(* Logix 5000 project; controller AMCI_3204_AOP_AOI_sample_RSLogix_V28 vendor 1 type 14 code 92 rev 28.11; software revision 28.00; part 3 of 3 *)

VAR_GLOBAL   (* controller tags *)
   blend_data_3204_ch1 : DINT[52];
        [11]   // Segment 3 speed
        [13]   // Segment 4 length
        [15]   // Segment 4 Acceleration or Deceleration
        [17]   // Segment 5 speed
        [1]   // Number of Segments
        [3]   // Final Segment's Deceleration Value and Type
        [5]   // Segment 1 speed
        [7]   // Segment 2 length
        [9]   // Segment 2 Acceleration or Deceleration
        [10]   // Segment 3 length
        [12]   // Segment 3 Acceleration or Deceleration
        [14]   // Segment 4 speed
        [16]   // Segment 5 length
        [18]   // Segment 5 Acceleraiton or Deceleration
        [0]   // channel number (1 or 2)
        [2]   // Acceleration Type
        [4]   // Segment 1 length
        [6]   // Segment 1 Acceleration or Deceleration
        [8]   // Segment 2 speed
   blend_message_3204_ch1 : MESSAGE;
        .DN   // set when blend data has been programmed
        MessageParameters(ServiceCode := 16#004c, LocalElement := blend_data_3204_ch1[0], ...)
   buffered_3204_data : DINT[20];
        [10].31   // AMCI 3204 ch 3 mode bit 1=config mode 0=command mode
        [0].1   // set when CCW motion is occurring on ch 1 of the AMCI 3204 module
        [10].13   // set when AMCI 3204 ch 3 has a configuration error
        [15].13   // set when AMCI 3204 ch 4 has a configuration error
        [15].31   // AMCI 3204 ch 4 mode bit 1=config mode 0=command mode
        [0].0   // set when CW motion is occurring on ch 1 of the AMCI 3204 module
        [0].7   // AMCI 3204 move complete bit
        [0].28   // set when AMCI 3204 ch 1 is disabled
        [5].28   // set when AMCI 3204 ch 2 is disabled
        [10].28   // Set when 3204 channel 3 is disabled
        [15].28   // Set when 3204 channel 4 is disabled
        [0].10   // AMCI 3204 ch 1 position invalid bit
        [0].13   // set when AMCI 3204 ch 1 has a configuration error
        [0].31   // AMCI 3204 ch 1 mode bit 1=config mode 0=command mode
        [5].13   // set when AMCI 3204 ch 2 has a configuration error
        [5].31   // AMCI 3204 ch 2 mode bit 1=config mode 0=command mode
   comment : INT;
   configure_3204_ch1 : DINT[5] := ([0] := -2146500561, [1] := 100);
        [1]   // starting speed
        [0]   // configuration word
   configure_3204_ch2 : DINT[5] := ([0] := -2146500561, [1] := 100);
        [1]   // starting speed
        [0]   // configuration word
   configure_3204_ch3 : DINT[5] := ([0] := -2146500561, [1] := 100);
        [0]   // configuration word
        [1]   // starting speed
   configure_3204_ch4 : DINT[5] := ([0] := -2146500561, [1] := 100);
        [0]   // configuration word
        [1]   // starting speed
   one_shot_1 : BOOL;
   one_shot_2 : BOOL;
   run_3204_ch1 : INT;   // 1=run relative move 2=CW Manual Move 3=CCW Manual Move 4=Reset Errors 5=Home CW 6=Preset 7=Program Blend 8=Run Blend CW
   run_3204_ch2 : INT;
   run_3204_ch3 : INT;
   run_3204_ch4 : INT;
END_VAR

PROGRAM MainProgram   (* main routine MainRoutine *)
VAR
   AMCI_3204_ch1_absolute_move_aoi : AMCI_3204_AOP_Absolute_Move;
   AMCI_3204_ch1_CCW_manual_move_AOI : AMCI_3204_AOP_Manual_Move_CCW;
   AMCI_3204_ch1_config_AOI : AMCI_3204_AOP_Configure;
   AMCI_3204_ch1_CW_manual_move_aoi : AMCI_3204_AOP_Manual_Move_CW;
   AMCI_3204_ch1_hold_AOI : AMCI_3204_AOP_Hold;
   AMCI_3204_ch1_Home_CCW_AOI : AMCI_3204_AOP_Home_CCW;
   AMCI_3204_ch1_Home_CW_AOI : AMCI_3204_AOP_Home_CW;
   AMCI_3204_ch1_immediate_stop_AOI : AMCI_3204_AOP_Immediate_Stop;
   AMCI_3204_ch1_preset_AOI : AMCI_3204_AOP_Preset;
   AMCI_3204_ch1_relative_move_AOI : AMCI_3204_AOP_Relative_Move;
   AMCI_3204_ch1_reset_errors_AOI : AMCI_3204_AOP_Reset_Errors;
   AMCI_3204_ch1_resume_AOI : AMCI_3204_AOP_Resume;
   AMCI_3204_ch1_run_blend : AMCI_3204_AOP_Run_Blend;
   AMCI_3204_ch2_config_AOI : AMCI_3204_AOP_Configure;
   AMCI_3204_ch2_CW_manual_move_aoi : AMCI_3204_AOP_Manual_Move_CW;
   AMCI_3204_ch2_relative_move_AOI : AMCI_3204_AOP_Relative_Move;
   AMCI_3204_ch3_config_AOI : AMCI_3204_AOP_Configure;
   AMCI_3204_ch3_CW_manual_move_aoi : AMCI_3204_AOP_Manual_Move_CW;
   AMCI_3204_ch3_relative_move_AOI : AMCI_3204_AOP_Relative_Move;
   AMCI_3204_ch4_config_AOI : AMCI_3204_AOP_Configure;
   AMCI_3204_ch4_CW_manual_move_aoi : AMCI_3204_AOP_Manual_Move_CW;
   AMCI_3204_ch4_relative_move_AOI : AMCI_3204_AOP_Relative_Move;
END_VAR

ROUTINE Channel_1_3204   (* ladder *)
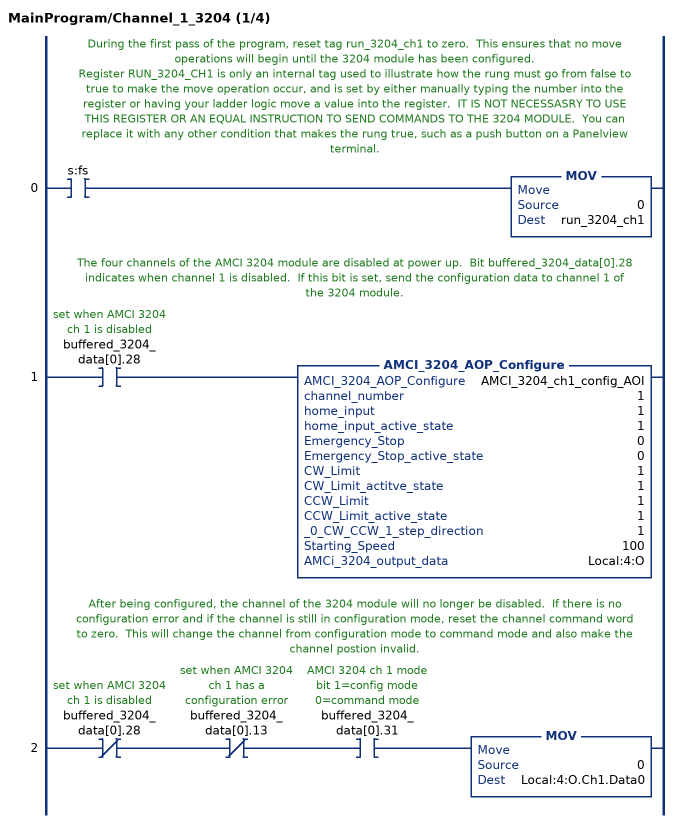
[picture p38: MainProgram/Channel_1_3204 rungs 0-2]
   // During the first pass of the program, reset tag run_3204_ch1 to zero.  This ensures that no move operations will begin until the 3204 module has been configured.
   // Register RUN_3204_CH1 is only an internal tag used to illustrate how the rung must go from false to true to make the move operation occur, and is set by either manually typing the number into the register or having your ladder logic move a value into the register.  IT IS NOT NECESSASRY TO USE THIS REGISTER OR AN EQUAL INSTRUCTION TO SEND COMMANDS TO THE 3204 MODULE.  You can replace it with any other condition that makes the rung true, such as a push button on a Panelview terminal.
   0: XIC(s:fs)MOV(0,run_3204_ch1);
   // The four channels of the AMCI 3204 module are disabled at power up.  Bit buffered_3204_data[0].28 indicates when channel 1 is disabled.  If this bit is set, send the configuration data to channel 1 of the 3204 module.
   1: XIC(buffered_3204_data[0].28)AMCI_3204_AOP_Configure(AMCI_3204_ch1_config_AOI,1,1,1,0,0,1,1,1,1,1,100,Local:4:O);
   // After being configured, the channel of the 3204 module will no longer be disabled.  If there is no configuration error and if the channel is still in configuration mode, reset the channel command word to zero.  This will change the channel from configuration mode to command mode and also make the channel postion invalid.
   2: XIO(buffered_3204_data[0].28)XIO(buffered_3204_data[0].13)XIC(buffered_3204_data[0].31)MOV(0,Local:4:O.Ch1.Data0);
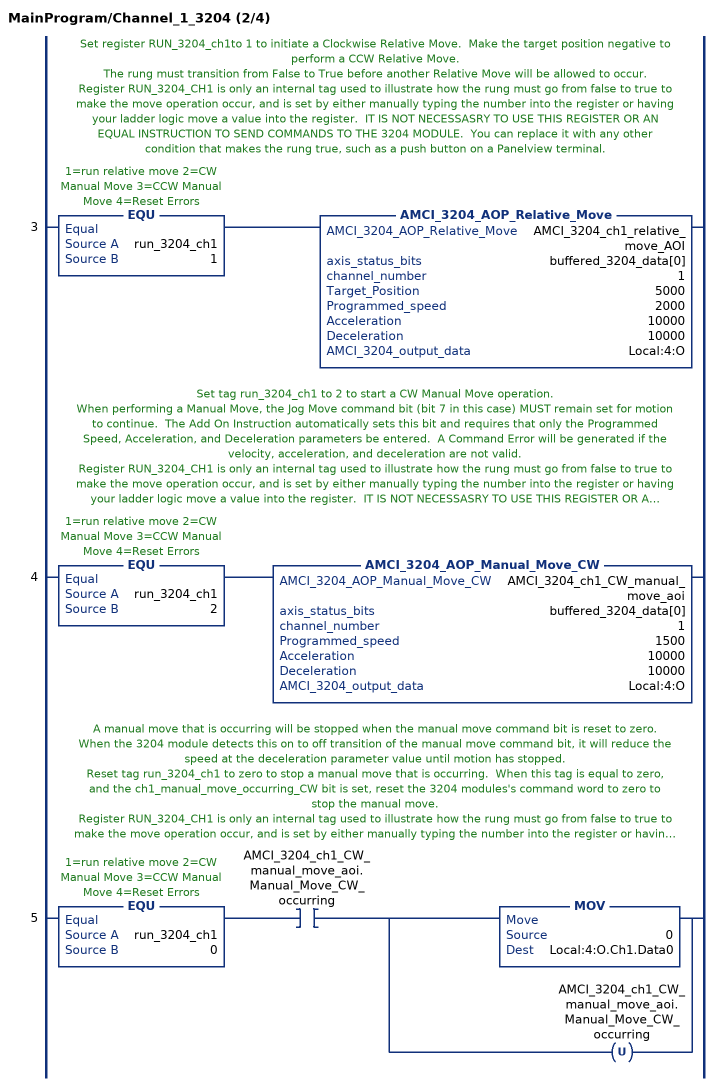
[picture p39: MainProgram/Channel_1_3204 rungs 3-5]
   // Set register RUN_3204_ch1to 1 to initiate a Clockwise Relative Move.  Make the target position negative to perform a CCW Relative Move.
   // The rung must transition from False to True before another Relative Move will be allowed to occur.
   // Register RUN_3204_CH1 is only an internal tag used to illustrate how the rung must go from false to true to make the move operation occur, and is set by either manually typing the number into the register or having your ladder logic move a value into the register.  IT IS NOT NECESSASRY TO USE THIS REGISTER OR AN EQUAL INSTRUCTION TO SEND COMMANDS TO THE 3204 MODULE.  You can replace it with any other condition that makes the rung true, such as a push button on a Panelview terminal.
   3: EQU(run_3204_ch1,1)AMCI_3204_AOP_Relative_Move(AMCI_3204_ch1_relative_move_AOI,buffered_3204_data[0],1,5000,2000,10000,10000,Local:4:O);
   // Set tag run_3204_ch1 to 2 to start a CW Manual Move operation.
   // When performing a Manual Move, the Jog Move command bit (bit 7 in this case) MUST remain set for motion to continue.  The Add On Instruction automatically sets this bit and requires that only the Programmed Speed, Acceleration, and Deceleration parameters be entered.  A Command Error will be generated if the velocity, acceleration, and deceleration are not valid.
   // Register RUN_3204_CH1 is only an internal tag used to illustrate how the rung must go from false to true to make the move operation occur, and is set by either manually typing the number into the register or having your ladder logic move a value into the register.  IT IS NOT NECESSASRY TO USE THIS REGISTER OR AN EQUAL INSTRUCTION TO SEND COMMANDS TO THE 3204 MODULE.  You can replace it with any other condition that makes the rung true, such as a push button on a Panelview terminal.
   4: EQU(run_3204_ch1,2)AMCI_3204_AOP_Manual_Move_CW(AMCI_3204_ch1_CW_manual_move_aoi,buffered_3204_data[0],1,1500,10000,10000,Local:4:O);
   // A manual move that is occurring will be stopped when the manual move command bit is reset to zero.  When the 3204 module detects this on to off transition of the manual move command bit, it will reduce the speed at the deceleration parameter value until motion has stopped.
   // Reset tag run_3204_ch1 to zero to stop a manual move that is occurring.  When this tag is equal to zero, and the ch1_manual_move_occurring_CW bit is set, reset the 3204 modules's command word to zero to stop the manual move.
   // Register RUN_3204_CH1 is only an internal tag used to illustrate how the rung must go from false to true to make the move operation occur, and is set by either manually typing the number into the register or having your ladder logic move a value into the register.  IT IS NOT NECESSASRY TO USE THIS REGISTER OR AN EQUAL INSTRUCTION TO SEND COMMANDS TO THE 3204 MODULE.  You can replace it with any other condition that makes the rung true, such as a push button on a Panelview terminal.
   5: EQU(run_3204_ch1,0)XIC(AMCI_3204_ch1_CW_manual_move_aoi.Manual_Move_CW_occurring)[MOV(0,Local:4:O.Ch1.Data0) ,OTU(AMCI_3204_ch1_CW_manual_move_aoi.Manual_Move_CW_occurring) ];
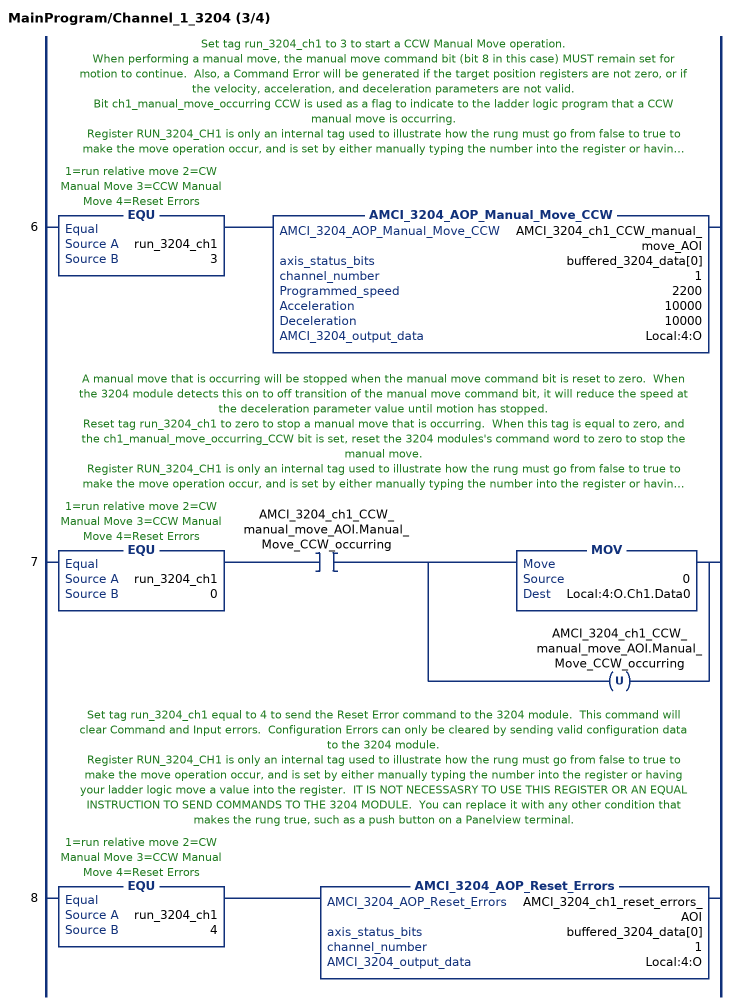
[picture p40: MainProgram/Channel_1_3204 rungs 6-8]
   // Set tag run_3204_ch1 to 3 to start a CCW Manual Move operation.
   // When performing a manual move, the manual move command bit (bit 8 in this case) MUST remain set for motion to continue.  Also, a Command Error will be generated if the target position registers are not zero, or if the velocity, acceleration, and deceleration parameters are not valid.
   // Bit ch1_manual_move_occurring CCW is used as a flag to indicate to the ladder logic program that a CCW manual move is occurring.
   // Register RUN_3204_CH1 is only an internal tag used to illustrate how the rung must go from false to true to make the move operation occur, and is set by either manually typing the number into the register or having your ladder logic move a value into the register.  IT IS NOT NECESSASRY TO USE THIS REGISTER OR AN EQUAL INSTRUCTION TO SEND COMMANDS TO THE 3204 MODULE.  You can replace it with any other condition that makes the rung true, such as a push button on a Panelview terminal.
   6: EQU(run_3204_ch1,3)AMCI_3204_AOP_Manual_Move_CCW(AMCI_3204_ch1_CCW_manual_move_AOI,buffered_3204_data[0],1,2200,10000,10000,Local:4:O);
   // A manual move that is occurring will be stopped when the manual move command bit is reset to zero.  When the 3204 module detects this on to off transition of the manual move command bit, it will reduce the speed at the deceleration parameter value until motion has stopped.
   // Reset tag run_3204_ch1 to zero to stop a manual move that is occurring.  When this tag is equal to zero, and the ch1_manual_move_occurring_CCW bit is set, reset the 3204 modules's command word to zero to stop the manual move.
   // Register RUN_3204_CH1 is only an internal tag used to illustrate how the rung must go from false to true to make the move operation occur, and is set by either manually typing the number into the register or having your ladder logic move a value into the register.  IT IS NOT NECESSASRY TO USE THIS REGISTER OR AN EQUAL INSTRUCTION TO SEND COMMANDS TO THE 3204 MODULE.  You can replace it with any other condition that makes the rung true, such as a push button on a Panelview terminal.
   7: EQU(run_3204_ch1,0)XIC(AMCI_3204_ch1_CCW_manual_move_AOI.Manual_Move_CCW_occurring)[MOV(0,Local:4:O.Ch1.Data0) ,OTU(AMCI_3204_ch1_CCW_manual_move_AOI.Manual_Move_CCW_occurring) ];
   // Set tag run_3204_ch1 equal to 4 to send the Reset Error command to the 3204 module.  This command will clear Command and Input errors.  Configuration Errors can only be cleared by sending valid configuration data to the 3204 module.
   // Register RUN_3204_CH1 is only an internal tag used to illustrate how the rung must go from false to true to make the move operation occur, and is set by either manually typing the number into the register or having your ladder logic move a value into the register.  IT IS NOT NECESSASRY TO USE THIS REGISTER OR AN EQUAL INSTRUCTION TO SEND COMMANDS TO THE 3204 MODULE.  You can replace it with any other condition that makes the rung true, such as a push button on a Panelview terminal.
   8: EQU(run_3204_ch1,4)AMCI_3204_AOP_Reset_Errors(AMCI_3204_ch1_reset_errors_AOI,buffered_3204_data[0],1,Local:4:O);
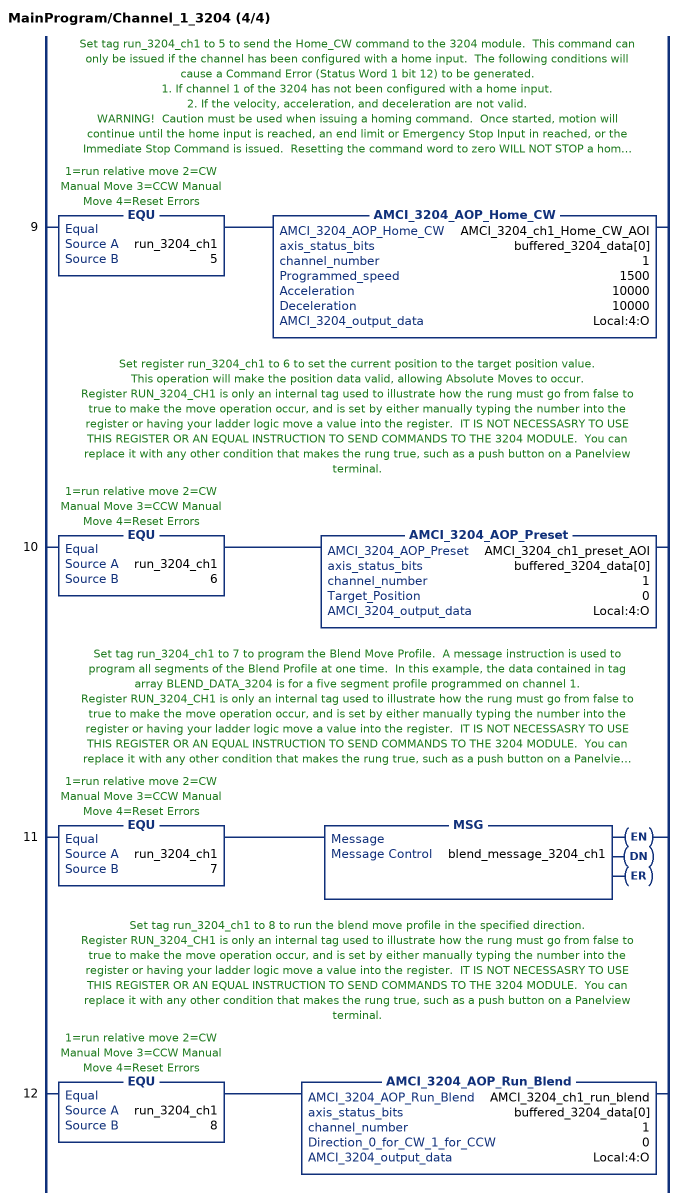
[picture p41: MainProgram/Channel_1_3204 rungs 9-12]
   // Set tag run_3204_ch1 to 5 to send the Home_CW command to the 3204 module.  This command can only be issued if the channel has been configured with a home input.  The following conditions will cause a Command Error (Status Word 1 bit 12) to be generated.
   // 1. If channel 1 of the 3204 has not been configured with a home input.
   // 2. If the velocity, acceleration, and deceleration are not valid.
   // WARNING!  Caution must be used when issuing a homing command.  Once started, motion will continue until the home input is reached, an end limit or Emergency Stop Input in reached, or the Immediate Stop Command is issued.  Resetting the command word to zero WILL NOT STOP a home operation.
   // Register RUN_3204_CH1 is only an internal tag used to illustrate how the rung must go from false to true to make the move operation occur, and is set by either manually typing the number into the register or having your ladder logic move a value into the register.  IT IS NOT NECESSASRY TO USE THIS REGISTER OR AN EQUAL INSTRUCTION TO SEND COMMANDS TO THE 3204 MODULE.  You can replace it with any other condition that makes the rung true, such as a push button on a Panelview terminal.
   9: EQU(run_3204_ch1,5)AMCI_3204_AOP_Home_CW(AMCI_3204_ch1_Home_CW_AOI,buffered_3204_data[0],1,1500,10000,10000,Local:4:O);
   // Set register run_3204_ch1 to 6 to set the current position to the target position value.
   // This operation will make the position data valid, allowing Absolute Moves to occur.
   // Register RUN_3204_CH1 is only an internal tag used to illustrate how the rung must go from false to true to make the move operation occur, and is set by either manually typing the number into the register or having your ladder logic move a value into the register.  IT IS NOT NECESSASRY TO USE THIS REGISTER OR AN EQUAL INSTRUCTION TO SEND COMMANDS TO THE 3204 MODULE.  You can replace it with any other condition that makes the rung true, such as a push button on a Panelview terminal.
   10: EQU(run_3204_ch1,6)AMCI_3204_AOP_Preset(AMCI_3204_ch1_preset_AOI,buffered_3204_data[0],1,0,Local:4:O);
   // Set tag run_3204_ch1 to 7 to program the Blend Move Profile.  A message instruction is used to program all segments of the Blend Profile at one time.  In this example, the data contained in tag array BLEND_DATA_3204 is for a five segment profile programmed on channel 1.
   // Register RUN_3204_CH1 is only an internal tag used to illustrate how the rung must go from false to true to make the move operation occur, and is set by either manually typing the number into the register or having your ladder logic move a value into the register.  IT IS NOT NECESSASRY TO USE THIS REGISTER OR AN EQUAL INSTRUCTION TO SEND COMMANDS TO THE 3204 MODULE.  You can replace it with any other condition that makes the rung true, such as a push button on a Panelview terminal.
   11: EQU(run_3204_ch1,7)MSG(blend_message_3204_ch1);
   // Set tag run_3204_ch1 to 8 to run the blend move profile in the specified direction.
   // Register RUN_3204_CH1 is only an internal tag used to illustrate how the rung must go from false to true to make the move operation occur, and is set by either manually typing the number into the register or having your ladder logic move a value into the register.  IT IS NOT NECESSASRY TO USE THIS REGISTER OR AN EQUAL INSTRUCTION TO SEND COMMANDS TO THE 3204 MODULE.  You can replace it with any other condition that makes the rung true, such as a push button on a Panelview terminal.
   12: EQU(run_3204_ch1,8)AMCI_3204_AOP_Run_Blend(AMCI_3204_ch1_run_blend,buffered_3204_data[0],1,0,Local:4:O);
END_ROUTINE

ROUTINE Channel_2_3204   (* ladder *)
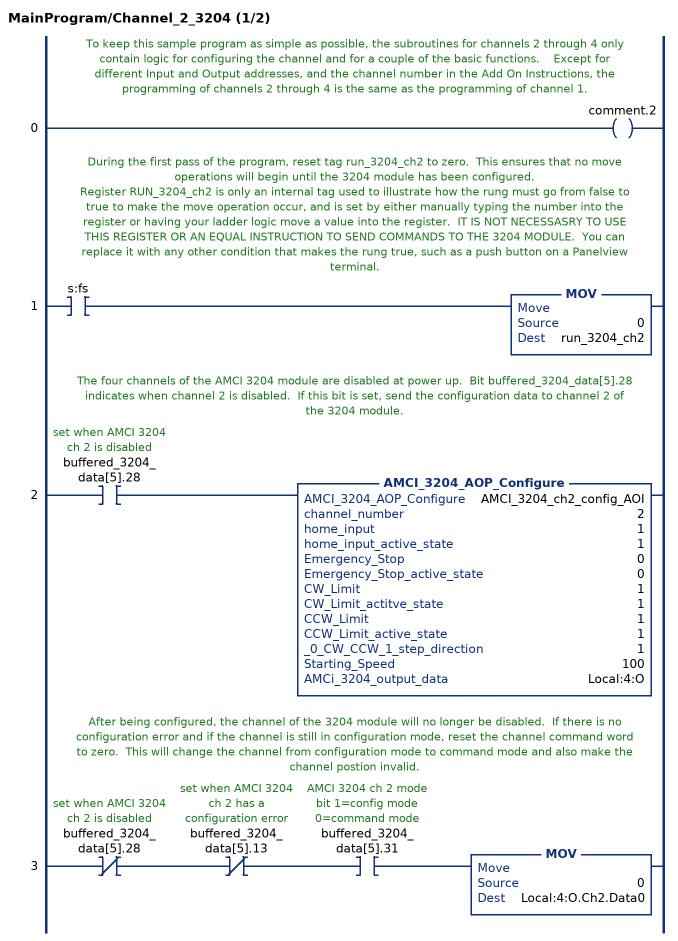
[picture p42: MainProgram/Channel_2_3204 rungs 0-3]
   // To keep this sample program as simple as possible, the subroutines for channels 2 through 4 only contain logic for configuring the channel and for a couple of the basic functions.    Except for different Input and Output addresses, and the channel number in the Add On Instructions, the programming of channels 2 through 4 is the same as the programming of channel 1.
   0: OTE(comment.2);
   // During the first pass of the program, reset tag run_3204_ch2 to zero.  This ensures that no move operations will begin until the 3204 module has been configured.
   // Register RUN_3204_ch2 is only an internal tag used to illustrate how the rung must go from false to true to make the move operation occur, and is set by either manually typing the number into the register or having your ladder logic move a value into the register.  IT IS NOT NECESSASRY TO USE THIS REGISTER OR AN EQUAL INSTRUCTION TO SEND COMMANDS TO THE 3204 MODULE.  You can replace it with any other condition that makes the rung true, such as a push button on a Panelview terminal.
   1: XIC(s:fs)MOV(0,run_3204_ch2);
   // The four channels of the AMCI 3204 module are disabled at power up.  Bit buffered_3204_data[5].28 indicates when channel 2 is disabled.  If this bit is set, send the configuration data to channel 2 of the 3204 module.
   2: XIC(buffered_3204_data[5].28)AMCI_3204_AOP_Configure(AMCI_3204_ch2_config_AOI,2,1,1,0,0,1,1,1,1,1,100,Local:4:O);
   // After being configured, the channel of the 3204 module will no longer be disabled.  If there is no configuration error and if the channel is still in configuration mode, reset the channel command word to zero.  This will change the channel from configuration mode to command mode and also make the channel postion invalid.
   3: XIO(buffered_3204_data[5].28)XIO(buffered_3204_data[5].13)XIC(buffered_3204_data[5].31)MOV(0,Local:4:O.Ch2.Data0);
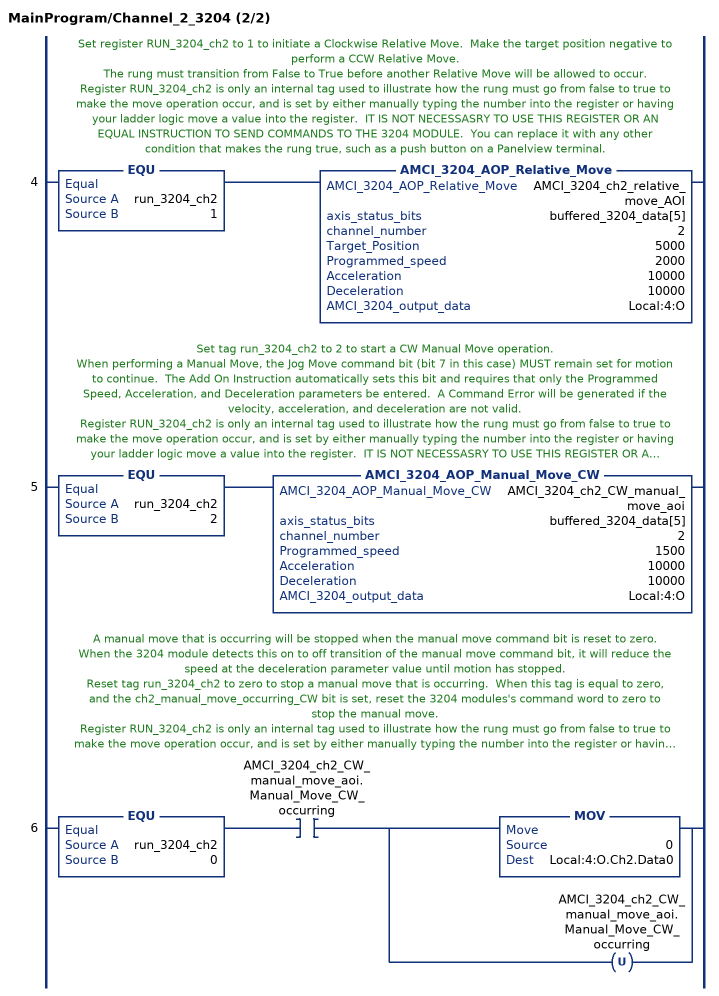
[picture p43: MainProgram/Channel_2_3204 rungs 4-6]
   // Set register RUN_3204_ch2 to 1 to initiate a Clockwise Relative Move.  Make the target position negative to perform a CCW Relative Move.
   // The rung must transition from False to True before another Relative Move will be allowed to occur.
   // Register RUN_3204_ch2 is only an internal tag used to illustrate how the rung must go from false to true to make the move operation occur, and is set by either manually typing the number into the register or having your ladder logic move a value into the register.  IT IS NOT NECESSASRY TO USE THIS REGISTER OR AN EQUAL INSTRUCTION TO SEND COMMANDS TO THE 3204 MODULE.  You can replace it with any other condition that makes the rung true, such as a push button on a Panelview terminal.
   4: EQU(run_3204_ch2,1)AMCI_3204_AOP_Relative_Move(AMCI_3204_ch2_relative_move_AOI,buffered_3204_data[5],2,5000,2000,10000,10000,Local:4:O);
   // Set tag run_3204_ch2 to 2 to start a CW Manual Move operation.
   // When performing a Manual Move, the Jog Move command bit (bit 7 in this case) MUST remain set for motion to continue.  The Add On Instruction automatically sets this bit and requires that only the Programmed Speed, Acceleration, and Deceleration parameters be entered.  A Command Error will be generated if the velocity, acceleration, and deceleration are not valid.
   // Register RUN_3204_ch2 is only an internal tag used to illustrate how the rung must go from false to true to make the move operation occur, and is set by either manually typing the number into the register or having your ladder logic move a value into the register.  IT IS NOT NECESSASRY TO USE THIS REGISTER OR AN EQUAL INSTRUCTION TO SEND COMMANDS TO THE 3204 MODULE.  You can replace it with any other condition that makes the rung true, such as a push button on a Panelview terminal.
   5: EQU(run_3204_ch2,2)AMCI_3204_AOP_Manual_Move_CW(AMCI_3204_ch2_CW_manual_move_aoi,buffered_3204_data[5],2,1500,10000,10000,Local:4:O);
   // A manual move that is occurring will be stopped when the manual move command bit is reset to zero.  When the 3204 module detects this on to off transition of the manual move command bit, it will reduce the speed at the deceleration parameter value until motion has stopped.
   // Reset tag run_3204_ch2 to zero to stop a manual move that is occurring.  When this tag is equal to zero, and the ch2_manual_move_occurring_CW bit is set, reset the 3204 modules's command word to zero to stop the manual move.
   // Register RUN_3204_ch2 is only an internal tag used to illustrate how the rung must go from false to true to make the move operation occur, and is set by either manually typing the number into the register or having your ladder logic move a value into the register.  IT IS NOT NECESSASRY TO USE THIS REGISTER OR AN EQUAL INSTRUCTION TO SEND COMMANDS TO THE 3204 MODULE.  You can replace it with any other condition that makes the rung true, such as a push button on a Panelview terminal.
   6: EQU(run_3204_ch2,0)XIC(AMCI_3204_ch2_CW_manual_move_aoi.Manual_Move_CW_occurring)[MOV(0,Local:4:O.Ch2.Data0) ,OTU(AMCI_3204_ch2_CW_manual_move_aoi.Manual_Move_CW_occurring) ];
END_ROUTINE

ROUTINE Channel_3_3204   (* ladder *)
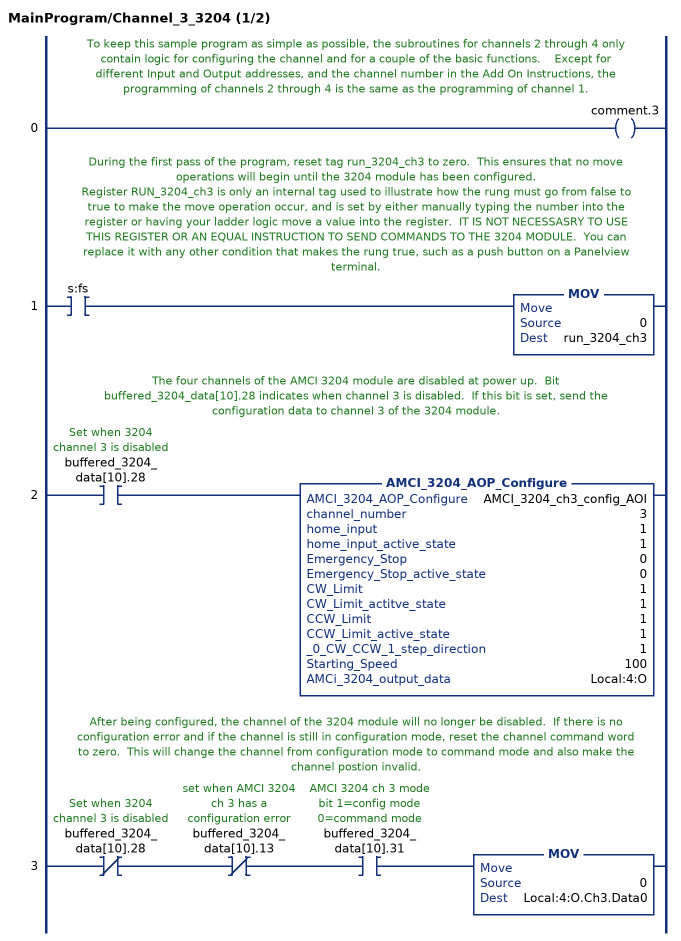
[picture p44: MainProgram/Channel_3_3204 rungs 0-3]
   // To keep this sample program as simple as possible, the subroutines for channels 2 through 4 only contain logic for configuring the channel and for a couple of the basic functions.    Except for different Input and Output addresses, and the channel number in the Add On Instructions, the programming of channels 2 through 4 is the same as the programming of channel 1.
   0: OTE(comment.3);
   // During the first pass of the program, reset tag run_3204_ch3 to zero.  This ensures that no move operations will begin until the 3204 module has been configured.
   // Register RUN_3204_ch3 is only an internal tag used to illustrate how the rung must go from false to true to make the move operation occur, and is set by either manually typing the number into the register or having your ladder logic move a value into the register.  IT IS NOT NECESSASRY TO USE THIS REGISTER OR AN EQUAL INSTRUCTION TO SEND COMMANDS TO THE 3204 MODULE.  You can replace it with any other condition that makes the rung true, such as a push button on a Panelview terminal.
   1: XIC(s:fs)MOV(0,run_3204_ch3);
   // The four channels of the AMCI 3204 module are disabled at power up.  Bit buffered_3204_data[10].28 indicates when channel 3 is disabled.  If this bit is set, send the configuration data to channel 3 of the 3204 module.
   2: XIC(buffered_3204_data[10].28)AMCI_3204_AOP_Configure(AMCI_3204_ch3_config_AOI,3,1,1,0,0,1,1,1,1,1,100,Local:4:O);
   // After being configured, the channel of the 3204 module will no longer be disabled.  If there is no configuration error and if the channel is still in configuration mode, reset the channel command word to zero.  This will change the channel from configuration mode to command mode and also make the channel postion invalid.
   3: XIO(buffered_3204_data[10].28)XIO(buffered_3204_data[10].13)XIC(buffered_3204_data[10].31)MOV(0,Local:4:O.Ch3.Data0);
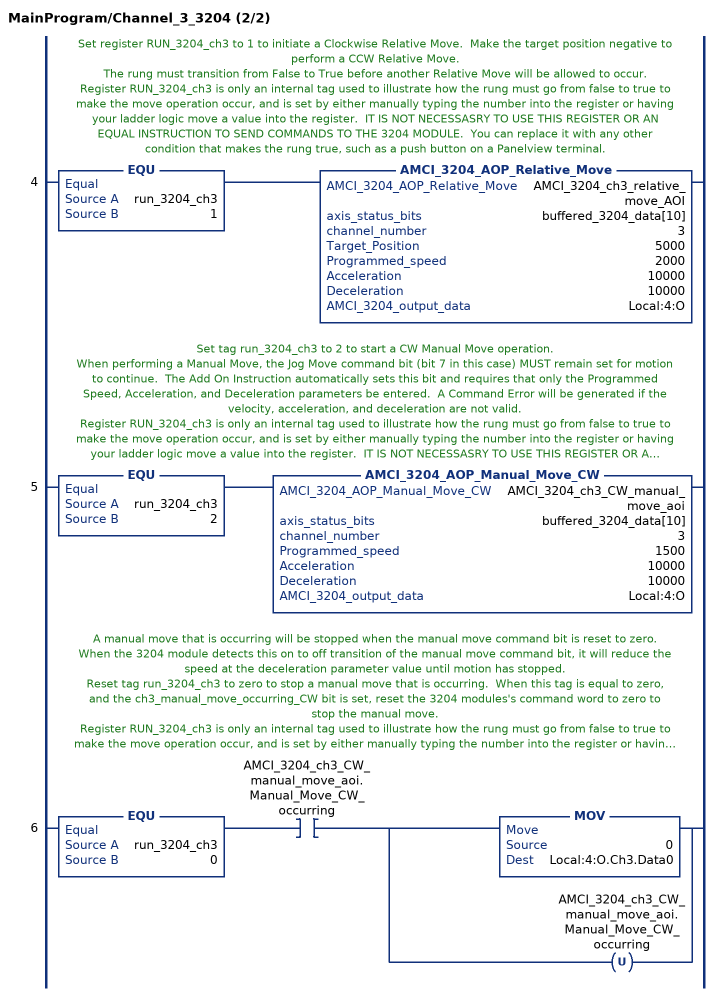
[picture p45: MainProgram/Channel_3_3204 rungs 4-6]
   // Set register RUN_3204_ch3 to 1 to initiate a Clockwise Relative Move.  Make the target position negative to perform a CCW Relative Move.
   // The rung must transition from False to True before another Relative Move will be allowed to occur.
   // Register RUN_3204_ch3 is only an internal tag used to illustrate how the rung must go from false to true to make the move operation occur, and is set by either manually typing the number into the register or having your ladder logic move a value into the register.  IT IS NOT NECESSASRY TO USE THIS REGISTER OR AN EQUAL INSTRUCTION TO SEND COMMANDS TO THE 3204 MODULE.  You can replace it with any other condition that makes the rung true, such as a push button on a Panelview terminal.
   4: EQU(run_3204_ch3,1)AMCI_3204_AOP_Relative_Move(AMCI_3204_ch3_relative_move_AOI,buffered_3204_data[10],3,5000,2000,10000,10000,Local:4:O);
   // Set tag run_3204_ch3 to 2 to start a CW Manual Move operation.
   // When performing a Manual Move, the Jog Move command bit (bit 7 in this case) MUST remain set for motion to continue.  The Add On Instruction automatically sets this bit and requires that only the Programmed Speed, Acceleration, and Deceleration parameters be entered.  A Command Error will be generated if the velocity, acceleration, and deceleration are not valid.
   // Register RUN_3204_ch3 is only an internal tag used to illustrate how the rung must go from false to true to make the move operation occur, and is set by either manually typing the number into the register or having your ladder logic move a value into the register.  IT IS NOT NECESSASRY TO USE THIS REGISTER OR AN EQUAL INSTRUCTION TO SEND COMMANDS TO THE 3204 MODULE.  You can replace it with any other condition that makes the rung true, such as a push button on a Panelview terminal.
   5: EQU(run_3204_ch3,2)AMCI_3204_AOP_Manual_Move_CW(AMCI_3204_ch3_CW_manual_move_aoi,buffered_3204_data[10],3,1500,10000,10000,Local:4:O);
   // A manual move that is occurring will be stopped when the manual move command bit is reset to zero.  When the 3204 module detects this on to off transition of the manual move command bit, it will reduce the speed at the deceleration parameter value until motion has stopped.
   // Reset tag run_3204_ch3 to zero to stop a manual move that is occurring.  When this tag is equal to zero, and the ch3_manual_move_occurring_CW bit is set, reset the 3204 modules's command word to zero to stop the manual move.
   // Register RUN_3204_ch3 is only an internal tag used to illustrate how the rung must go from false to true to make the move operation occur, and is set by either manually typing the number into the register or having your ladder logic move a value into the register.  IT IS NOT NECESSASRY TO USE THIS REGISTER OR AN EQUAL INSTRUCTION TO SEND COMMANDS TO THE 3204 MODULE.  You can replace it with any other condition that makes the rung true, such as a push button on a Panelview terminal.
   6: EQU(run_3204_ch3,0)XIC(AMCI_3204_ch3_CW_manual_move_aoi.Manual_Move_CW_occurring)[MOV(0,Local:4:O.Ch3.Data0) ,OTU(AMCI_3204_ch3_CW_manual_move_aoi.Manual_Move_CW_occurring) ];
END_ROUTINE

ROUTINE Channel_4_3204   (* ladder *)
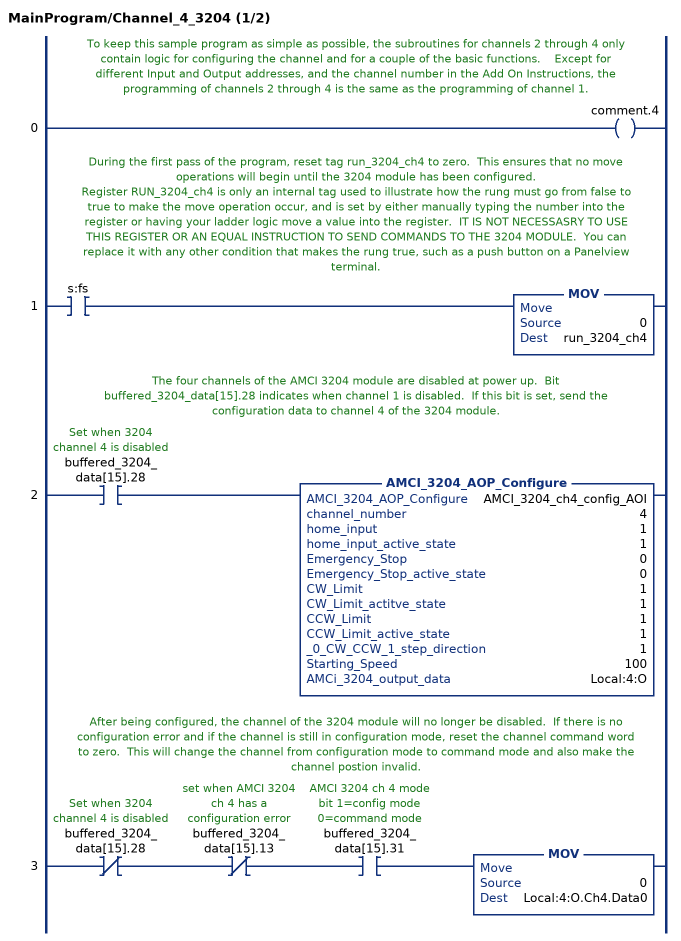
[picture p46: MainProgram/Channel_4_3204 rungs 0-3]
   // To keep this sample program as simple as possible, the subroutines for channels 2 through 4 only contain logic for configuring the channel and for a couple of the basic functions.    Except for different Input and Output addresses, and the channel number in the Add On Instructions, the programming of channels 2 through 4 is the same as the programming of channel 1.
   0: OTE(comment.4);
   // During the first pass of the program, reset tag run_3204_ch4 to zero.  This ensures that no move operations will begin until the 3204 module has been configured.
   // Register RUN_3204_ch4 is only an internal tag used to illustrate how the rung must go from false to true to make the move operation occur, and is set by either manually typing the number into the register or having your ladder logic move a value into the register.  IT IS NOT NECESSASRY TO USE THIS REGISTER OR AN EQUAL INSTRUCTION TO SEND COMMANDS TO THE 3204 MODULE.  You can replace it with any other condition that makes the rung true, such as a push button on a Panelview terminal.
   1: XIC(s:fs)MOV(0,run_3204_ch4);
   // The four channels of the AMCI 3204 module are disabled at power up.  Bit buffered_3204_data[15].28 indicates when channel 1 is disabled.  If this bit is set, send the configuration data to channel 4 of the 3204 module.
   2: XIC(buffered_3204_data[15].28)AMCI_3204_AOP_Configure(AMCI_3204_ch4_config_AOI,4,1,1,0,0,1,1,1,1,1,100,Local:4:O);
   // After being configured, the channel of the 3204 module will no longer be disabled.  If there is no configuration error and if the channel is still in configuration mode, reset the channel command word to zero.  This will change the channel from configuration mode to command mode and also make the channel postion invalid.
   3: XIO(buffered_3204_data[15].28)XIO(buffered_3204_data[15].13)XIC(buffered_3204_data[15].31)MOV(0,Local:4:O.Ch4.Data0);
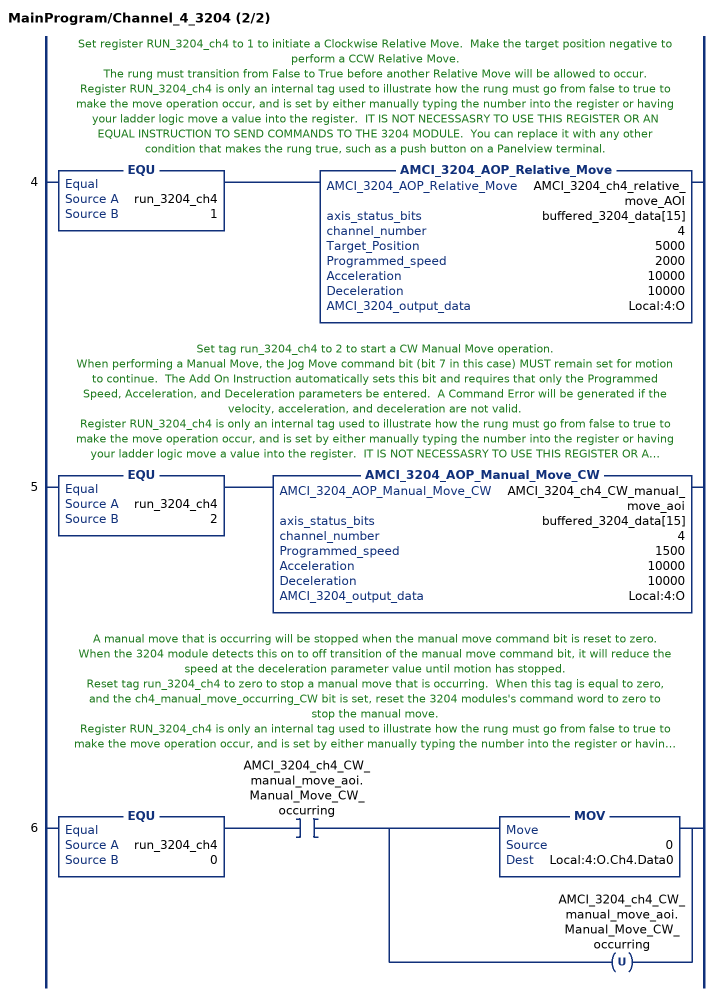
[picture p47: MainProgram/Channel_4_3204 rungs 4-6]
   // Set register RUN_3204_ch4 to 1 to initiate a Clockwise Relative Move.  Make the target position negative to perform a CCW Relative Move.
   // The rung must transition from False to True before another Relative Move will be allowed to occur.
   // Register RUN_3204_ch4 is only an internal tag used to illustrate how the rung must go from false to true to make the move operation occur, and is set by either manually typing the number into the register or having your ladder logic move a value into the register.  IT IS NOT NECESSASRY TO USE THIS REGISTER OR AN EQUAL INSTRUCTION TO SEND COMMANDS TO THE 3204 MODULE.  You can replace it with any other condition that makes the rung true, such as a push button on a Panelview terminal.
   4: EQU(run_3204_ch4,1)AMCI_3204_AOP_Relative_Move(AMCI_3204_ch4_relative_move_AOI,buffered_3204_data[15],4,5000,2000,10000,10000,Local:4:O);
   // Set tag run_3204_ch4 to 2 to start a CW Manual Move operation.
   // When performing a Manual Move, the Jog Move command bit (bit 7 in this case) MUST remain set for motion to continue.  The Add On Instruction automatically sets this bit and requires that only the Programmed Speed, Acceleration, and Deceleration parameters be entered.  A Command Error will be generated if the velocity, acceleration, and deceleration are not valid.
   // Register RUN_3204_ch4 is only an internal tag used to illustrate how the rung must go from false to true to make the move operation occur, and is set by either manually typing the number into the register or having your ladder logic move a value into the register.  IT IS NOT NECESSASRY TO USE THIS REGISTER OR AN EQUAL INSTRUCTION TO SEND COMMANDS TO THE 3204 MODULE.  You can replace it with any other condition that makes the rung true, such as a push button on a Panelview terminal.
   5: EQU(run_3204_ch4,2)AMCI_3204_AOP_Manual_Move_CW(AMCI_3204_ch4_CW_manual_move_aoi,buffered_3204_data[15],4,1500,10000,10000,Local:4:O);
   // A manual move that is occurring will be stopped when the manual move command bit is reset to zero.  When the 3204 module detects this on to off transition of the manual move command bit, it will reduce the speed at the deceleration parameter value until motion has stopped.
   // Reset tag run_3204_ch4 to zero to stop a manual move that is occurring.  When this tag is equal to zero, and the ch4_manual_move_occurring_CW bit is set, reset the 3204 modules's command word to zero to stop the manual move.
   // Register RUN_3204_ch4 is only an internal tag used to illustrate how the rung must go from false to true to make the move operation occur, and is set by either manually typing the number into the register or having your ladder logic move a value into the register.  IT IS NOT NECESSASRY TO USE THIS REGISTER OR AN EQUAL INSTRUCTION TO SEND COMMANDS TO THE 3204 MODULE.  You can replace it with any other condition that makes the rung true, such as a push button on a Panelview terminal.
   6: EQU(run_3204_ch4,0)XIC(AMCI_3204_ch4_CW_manual_move_aoi.Manual_Move_CW_occurring)[MOV(0,Local:4:O.Ch4.Data0) ,OTU(AMCI_3204_ch4_CW_manual_move_aoi.Manual_Move_CW_occurring) ];
END_ROUTINE

ROUTINE MainRoutine   (* ladder *)
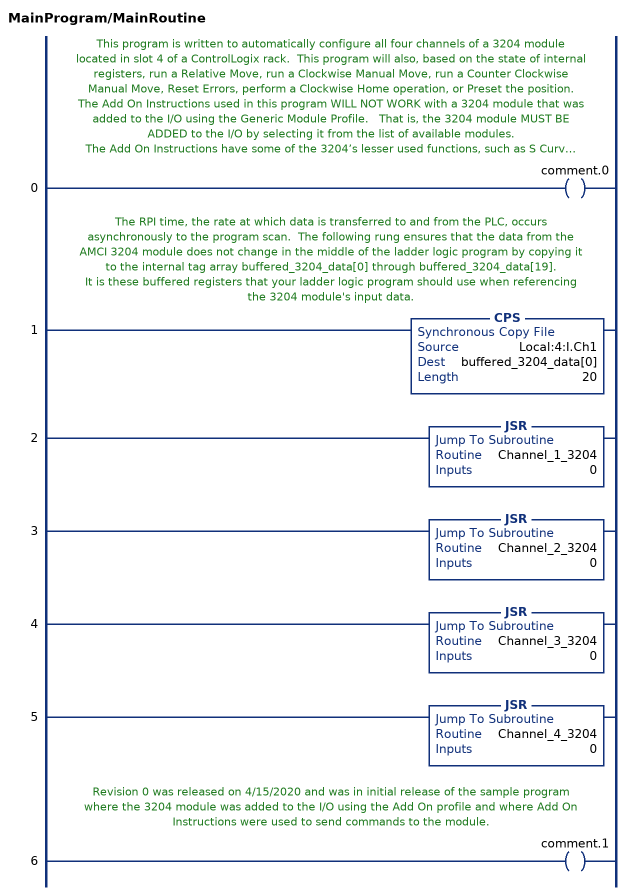
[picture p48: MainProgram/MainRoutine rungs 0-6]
   // This program is written to automatically configure all four channels of a 3204 module located in slot 4 of a ControlLogix rack.  This program will also, based on the state of internal registers, run a Relative Move, run a Clockwise Manual Move, run a Counter Clockwise Manual Move, Reset Errors, perform a Clockwise Home operation, or Preset the position.
   // The Add On Instructions used in this program WILL NOT WORK with a 3204 module that was added to the I/O using the Generic Module Profile.   That is, the 3204 module MUST BE ADDED to the I/O by selecting it from the list of available modules.
   // The Add On Instructions have some of the 3204’s lesser used functions, such as S Curve Acceleration, hidden.  The Add On Instructions are not locked or protected and, if desired, these functions can be enabled and made visible.
   // To keep this sample program as simple as possible, the subroutines for channels 2 through 4 only contain logic for configuring the channel and for a couple of the basic functions.    Except for different Input and Output addresses, the programming of channels 2 through 4 is the same as the programming of channel 1.
   // This program also contains logic to program and perform blend moves.  This logic is optional and if not needed, can be deleted or ignored.
   // Registers RUN_3204_ch1 to RUN_3204_ch4 are only internal tags used to illustrate how the rung must go from false to true to make the move operation occur, and is set by either manually typing the number into the register or having your ladder logic move a value into the register.  IT IS NOT NECESSASRY TO USE these REGISTER OR AN EQUAL INSTRUCTION TO SEND COMMANDS TO THE 3204 MODULE.  You can replace it with any other condition that makes the rung true, such as a push button on a Panelview terminal.
   0: OTE(comment.0);
   // The RPI time, the rate at which data is transferred to and from the PLC, occurs asynchronously to the program scan.  The following rung ensures that the data from the AMCI 3204 module does not change in the middle of the ladder logic program by copying it to the internal tag array buffered_3204_data[0] through buffered_3204_data[19].
   // It is these buffered registers that your ladder logic program should use when referencing the 3204 module's input data.
   1: CPS(Local:4:I.Ch1,buffered_3204_data[0],20);
   2: JSR(Channel_1_3204,0);
   3: JSR(Channel_2_3204,0);
   4: JSR(Channel_3_3204,0);
   5: JSR(Channel_4_3204,0);
   // Revision 0 was released on 4/15/2020 and was in initial release of the sample program where the 3204 module was added to the I/O using the Add On profile and where Add On Instructions were used to send commands to the module.
   6: OTE(comment.1);
END_ROUTINE
END_PROGRAM
